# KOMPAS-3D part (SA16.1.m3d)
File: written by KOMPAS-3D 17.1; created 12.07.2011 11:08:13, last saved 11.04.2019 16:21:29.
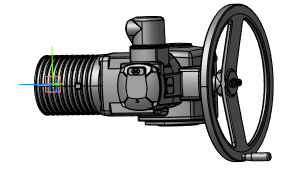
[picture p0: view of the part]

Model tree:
1. Плоскость XY
2. Плоскость ZX
3. Плоскость ZY
4. Ось X
5. Ось Y
6. Ось Z
7. Начало координат
8. Операция без истории:2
